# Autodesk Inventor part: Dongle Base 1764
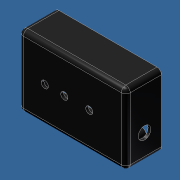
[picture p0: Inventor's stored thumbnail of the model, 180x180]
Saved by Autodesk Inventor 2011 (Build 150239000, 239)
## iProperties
Created: 2010-01
Part Number: Dongle Base 1764
Document SubType Name: Modeling
Designer: jgehrig
Density: 1 g/cm^3
Author: jgehrig
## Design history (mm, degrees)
sketch "Sketch1"
  geometry: L1 (-31.135, 11.158)-(45.065, 11.158); L2 (45.065, 11.158)-(45.065, -39.642); L3 (45.065, -39.642)-(-31.135, -39.642); L4 (-31.135, -39.642)-(-31.135, 11.158); 1 further point
  constraints: 8 end point, 2 parallel, 1 horizontal, 1 perpendicular
  dimensions: "d0" = 76.2 distance of L1.start L1.end; "d1" = 50.8 distance of L3.end L1.start
extrude "Extrusion1" new body sketch "Sketch1" distance "d2" = 25.4; taper "d3" = 0 deg
fillet "Fillet1" dims "d4" = 3.175
shell "Shell1" dims "d5" = 1.905
sketch "Sketch2"
  geometry: L1 (-27.96, -36.467)-(-27.96, 7.983) reference; C1 r 2.54 at (1.25, -14.242); C2 r 2.54 at (19.03, -14.242); C3 r 2.54 at (-12.72, -14.242); 1 further point
  constraints: 3 centre point
  dimensions: "d6" = 5.08 diameter of C1; "d7" = 5.08 diameter of C3; "d8" = 5.08 diameter of C2; "d9" = 15.24 distance from line of L1 C3.centre; "d10" = 13.97 distance of C3.centre C1.centre; "d11" = 17.78 distance of C1.centre C2.centre
extrude "Extrusion2" cut sketch "Sketch2" distance "d12" = 25.4; taper "d13" = 0 deg
sketch "Sketch3"
  geometry: L1 (0, -44.45)-(69.85, -44.45) reference; L2 (69.85, -44.45)-(69.85, 0) reference; L3 (71.12, 0)-(71.12, -44.45) reference; L4 (69.85, -45.72)-(0, -45.72) reference; C1 r 3.175 at (63.5, -38.1); C2 r 1.27 at (63.5, -38.1); C3 r 3.175 at (6.35, -38.1); C4 r 1.27 at (6.35, -38.1); C5 r 3.175 at (63.5, -6.35); C6 r 1.27 at (63.5, -6.35); C7 r 3.175 at (6.35, -6.35); C8 r 1.27 at (6.35, -6.35); 1 further point
  constraints: 8 centre point, 4 coincident, 1 horizontal, 1 vertical, 12 other
  dimensions: "d14" = 6.35 diameter of C1; "d15" = 2.54 diameter of C2; "d20" = 57.15 distance of C1.centre C3.centre; "d23" = 31.75 distance of C1.centre C5.centre; "d41" = 7.62 distance from line of L3 C1.centre; "d42" = 7.62 distance from line of L4 C1.centre
extrude "Extrusion3" join sketch "Sketch3" distance "d26" = 19.05; taper "d27" = 0 deg
thread "Thread1" dims "d28" = 25.4, "d29" = 0
thread "Thread2" dims "d30" = 25.4, "d31" = 0
thread "Thread3" dims "d32" = 25.4, "d33" = 0
thread "Thread4" dims "d34" = 25.4, "d35" = 0
sketch "Sketch4"
  geometry: L1 (-22.225, 0)-(-22.225, 44.45) reference; L2 (0, 0)-(-22.225, 0) reference; C1 r 4.445 at (-12.065, 14.605); 1 further point
  constraints: 1 centre point
  dimensions: "d36" = 8.89 diameter of C1; "d37" = 14.605 distance from line of L2 C1.centre; "d38" = 10.16 distance from line of L1 C1.centre
extrude "Extrusion4" cut sketch "Sketch4" distance "d39" = 6.35; taper "d40" = 0 deg
body "Solid1"
